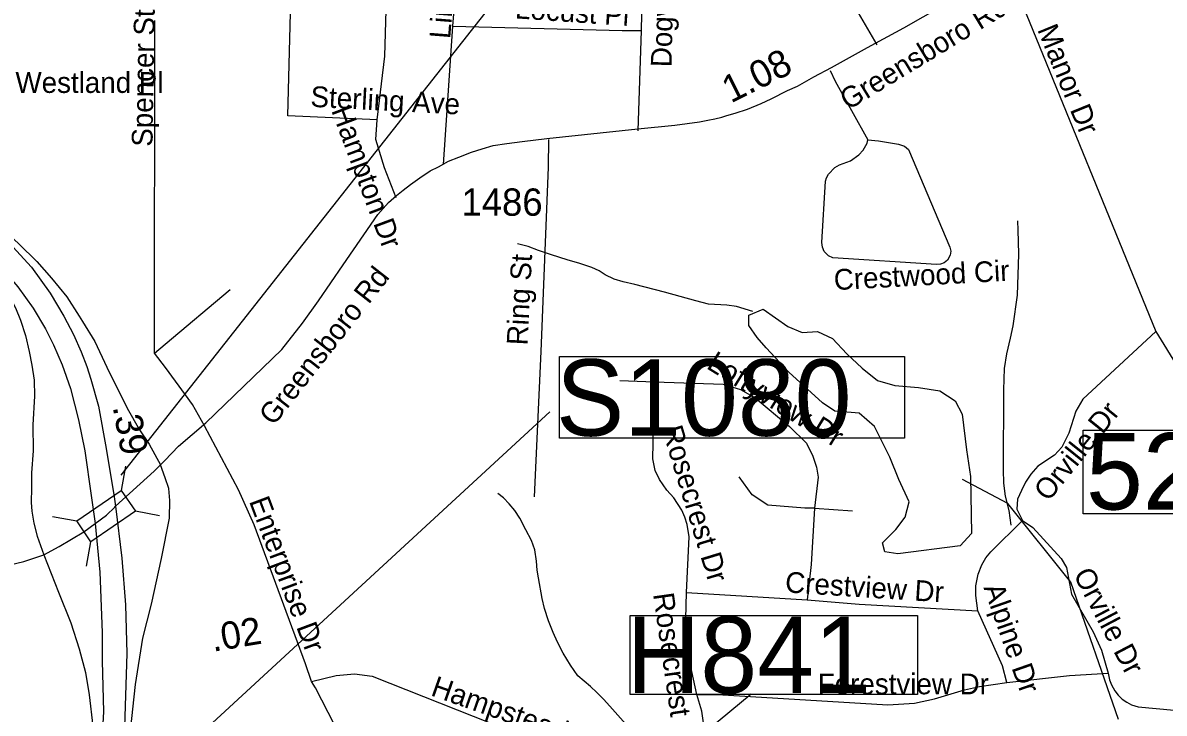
# Model space of a CAD drawing. Extents: x 1662474 to 1856135, y 779280 to 917889.
# Drawn here: x 1711418 to 1716644, y 813062 to 816221 of the extents above; entities that cross this region are included whole.
import ezdxf

# ---------------------------------------------------------------- set-up
doc = ezdxf.new("R2010")
doc.units = 0
for name, color, linetype in [('Exist Hydrographic Misc Water Feature', 7, 'Continuous'), ('Exist Hydrographic Pond Under 1500 Sq Ft', 7, 'Continuous'), ('Exist Road Non-System Structure Non-Sys NCDOT Number Label', 7, 'Continuous'), ('Exist Road Non-System Type 51', 7, 'Continuous'), ('Exist Road Non-System Type 51 Label', 7, 'Continuous'), ('Exist Road Primary Interstate Ramp 1 Lane Attributed', 7, 'Continuous'), ('Exist Road Primary US Divided Attributed', 7, 'Continuous'), ('Exist Road Primary US Mileage Hundredths English Label', 7, 'Continuous'), ('Exist Road Primary US Structure Ovrhead Sign CELL', 7, 'Continuous'), ('Exist Road Secondary Mileage Hundredths English Label', 7, 'Continuous'), ('Exist Road Secondary Structure Standard Bridge CELL', 7, 'Continuous'), ('Exist Road Secondary Structure Standard Bridge Number Label', 7, 'Continuous'), ('Exist Road Secondary Type 51 Attributed', 7, 'Continuous'), ('Exist Road Secondary Type 51 Label', 7, 'Continuous'), ('Exist Road Secondary Type 51 Number Label', 7, 'Continuous')]:
    doc.layers.add(name, color=color, linetype=linetype)

msp = doc.modelspace()

# ---------------------------------------------------------------- linework, layer by layer
at = {"layer": 'Exist Hydrographic Misc Water Feature'}
msp.add_line((1714761.2, 814899.8), (1714685.4, 814922.6), dxfattribs=at)
for points in [[(1715944.3, 813922.4), (1715934.9, 813988.4), (1715917.6, 814054.6), (1715910.2, 814114.7), (1715908.6, 814174.7), (1715910.2, 814540.8), (1715913.1, 814638.9), (1715923.7, 814706.7), (1715940.4, 814778.6), (1715952.9, 814834.5), (1715972.3, 814974.4), (1715978.1, 815162.4), (1715976.5, 815218.4), (1715975.1, 815272.4), (1715973.5, 815314.5)], [(1714685.4, 814922.6), (1714641.4, 814929), (1714557.3, 814933.8), (1714499.5, 814948.3), (1714355.9, 814987.7), (1714220.1, 815023), (1714166.2, 815035.5), (1714126.4, 815047.9), (1714084.5, 815068.3), (1714056.7, 815086.6), (1714022.9, 815100.9), (1713969.1, 815119.4), (1713911.1, 815136), (1713839.4, 815158.6), (1713779.5, 815179.2), (1713731.6, 815197.7), (1713683.7, 815210.1)], [(1716435.3, 813033.3), (1716216.3, 813661.3), (1715928.3, 814021.7), (1715720.3, 814131)], [(1714266.3, 812913.9), (1714105.8, 813093.4), (1714076.3, 813125.7), (1714046.5, 813156), (1714016.7, 813184.3), (1713988.8, 813208.6), (1713959.1, 813232.9), (1713925.6, 813281.2), (1713892.2, 813335.6), (1713866.6, 813385.8), (1713846.9, 813430), (1713825.5, 813484.2), (1713806, 813540.4), (1713796.5, 813586.5), (1713779.4, 813680.7), (1713773.6, 813716.8), (1713769.9, 813756.8), (1713762.5, 813808.9), (1713747, 813851.1), (1713721.4, 813901.3), (1713693.9, 813953.6), (1713670.3, 813989.9), (1713644.5, 814020.1), (1713618.7, 814046.4), (1713592.9, 814066.6)]]:
    msp.add_lwpolyline(points, dxfattribs=at)
at = {"layer": 'Exist Hydrographic Pond Under 1500 Sq Ft'}
msp.add_lwpolyline([(1715757, 814145.2), (1715761.7, 813883.7), (1715710.3, 813827.6), (1715425.2, 813790.3), (1715364.5, 813799.6), (1715355.1, 813841.6), (1715415.9, 813902.3), (1715457.9, 813958.4), (1715476.6, 814028.5), (1715429.9, 814131.2), (1715387.8, 814234), (1715317.7, 814374.1), (1715247.6, 814434.8), (1715135.5, 814444.2), (1715079.4, 814481.5), (1714925.2, 814621.6), (1714822.4, 814733.7), (1714780.3, 814780.4), (1714742.9, 814836.5), (1714742.9, 814883.2), (1714808.4, 814911.2), (1714920.5, 814831.8), (1714985.9, 814803.8), (1715056, 814808.5), (1715126.1, 814775.8), (1715191.6, 814705.7), (1715261.7, 814640.3), (1715331.7, 814584.3), (1715411.2, 814560.9), (1715518.7, 814551.6), (1715616.8, 814537.6), (1715686.9, 814490.9), (1715719.6, 814430.1), (1715738.3, 814266.7), (1715757, 814145.2)], dxfattribs=at)
at = {"layer": 'Exist Road Non-System Structure Non-Sys NCDOT Number Label'}
msp.add_line((1711805.1, 810722.8), (1714752.6, 813149.3), dxfattribs=at)
msp.add_lwpolyline([(1714198.2, 813508.5), (1715515.3, 813508.5), (1715515.3, 813147.3), (1714198.2, 813147.3)], close=True, dxfattribs=at)
at = {"layer": 'Exist Road Non-System Type 51'}
for p, q in [((1713386.9, 816205.4), (1713415.4, 816558.2)), ((1714251.1, 816186.8), (1714259.2, 816535.9)), ((1715928.5, 816468.9), (1716606.5, 814808.9)), ((1712020.5, 814709.7), (1712021.8, 816231.2)), ((1713344.9, 815572.6), (1713386.9, 816205.4)), ((1714235.9, 815727.2), (1714251.1, 816186.8)), ((1716606.5, 814808.9), (1716708.4, 814641.7)), ((1714151.9, 814583.7), (1714311, 814577.9)), ((1715042.8, 813999.4), (1715216.8, 813986.9)), ((1714457.6, 813614.1), (1715009.4, 813580))]:
    msp.add_line(p, q, dxfattribs=at)
for points in [[(1713039.9, 815777.1), (1712630.9, 815794.9), (1712662.1, 816972.6)], [(1713039.9, 815777.1), (1713075.4, 816068.7), (1713102.1, 816964.2)], [(1715186.6, 816353.7), (1715194.1, 816352.4), (1715231.6, 816285.8), (1715328.2, 816120.1)], [(1713386.9, 816205.4), (1714161.9, 816186.8), (1714251.1, 816186.8)], [(1715115.4, 816003.4), (1715136.9, 815954.5), (1715286.6, 815685.2)], [(1713127.2, 815419.6), (1713073.5, 815558.2), (1713034.1, 815687.6), (1713039.9, 815777.1)], [(1713761.4, 814051.9), (1713792.1, 814716.2), (1713825.4, 815560), (1713827, 815687.1)], [(1715286.6, 815685.2), (1715335.4, 815681), (1715428.2, 815666.1), (1715455.1, 815656.4), (1715473.4, 815641.7), (1715663.1, 815194.9), (1715666.6, 815176.4), (1715664, 815157.7), (1715651.9, 815135.6), (1715636.9, 815123.2), (1715619.9, 815116.8), (1715601, 815114.9), (1715127.2, 815146.1), (1715107.6, 815154.8), (1715087.6, 815174.5), (1715078.9, 815193.9), (1715076.6, 815215.2), (1715092.9, 815495.8), (1715097.6, 815512), (1715107, 815529.1), (1715136.4, 815559.5), (1715157.6, 815570.8), (1715207.2, 815588.9), (1715246.4, 815617.2), (1715265.9, 815637.7), (1715284.1, 815670.2), (1715286.6, 815685.2)], [(1712020.5, 814709.7), (1712070.4, 814749.9), (1712367.1, 815001)], [(1716606.5, 814808.9), (1716272.4, 814498.1), (1716240.1, 814443.2), (1716208.1, 814343.5), (1716175.8, 814278.9), (1716141.9, 814241.9), (1716066.1, 814192.1), (1716034.1, 814155.4), (1716009.6, 814118.1), (1715990.2, 814081), (1715972.6, 814040.6), (1715969.5, 813995.2), (1715996.2, 813944)], [(1712249.1, 814377.4), (1712195.5, 814474.8), (1712163.2, 814519.1), (1712071.6, 814644.2), (1712020.5, 814709.7)], [(1714457.6, 813614.1), (1714469.2, 813868.2), (1714459.9, 813925.4), (1714449.6, 813958.8), (1714436.1, 813990.8), (1714399.1, 814046.9), (1714367.1, 814082.6), (1714333, 814130.7), (1714314.1, 814171.6), (1714302.1, 814225.4), (1714311, 814577.9)], [(1714311, 814577.9), (1714624.6, 814566.9), (1714704.4, 814542.8), (1714770.9, 814505.2), (1714928, 814373.7), (1715006.2, 814297.4), (1715035.4, 814237.8), (1715051.9, 814187.6), (1715059.5, 814141.9), (1715042.8, 813999.4)], [(1712739.6, 813206.2), (1712712.9, 813287.4), (1712476.6, 813923.4), (1712405.5, 814083.2), (1712249.1, 814377.4)], [(1715042.8, 813999.4), (1714998.4, 814000.2), (1714828.6, 814013.9), (1714757.6, 814060.9), (1714697.4, 814143.5)], [(1715042.8, 813999.4), (1715028, 813741.7), (1715009.4, 813580)], [(1715790.5, 813529.6), (1715781, 813599.7), (1715781.2, 813645.1), (1715791.8, 813698.4), (1715809.1, 813740.7), (1715828, 813772.1), (1715850.9, 813799.9), (1715996.2, 813944)], [(1715996.2, 813944), (1716043.2, 813912), (1716172.9, 813769.8), (1716196.8, 813728), (1716219.4, 813606.5), (1716318.9, 813433.6), (1716356.9, 813350.4), (1716387.4, 813244.9)], [(1714504.6, 813147.2), (1714481.6, 813251.7), (1714459.5, 813378.4), (1714453.5, 813493.7), (1714457.6, 813614.1)], [(1715009.4, 813580), (1715247.1, 813560.6), (1715790.5, 813529.6)], [(1715924.4, 813201.2), (1715903.6, 813278.7), (1715790.5, 813529.6)], [(1712739.6, 813206.2), (1712853.2, 813234.1), (1712936.8, 813240.9), (1713018.1, 813230.7), (1713561.4, 813016.5)], [(1715924.4, 813201.2), (1716211.1, 813233.6), (1716387.4, 813244.9)], [(1716387.4, 813244.9), (1716393.9, 813213.9), (1716402.5, 813190.5), (1716418, 813163.2), (1716434, 813143.8), (1716452.1, 813125.9), (1716472.9, 813111.5), (1716495.1, 813100.2), (1716525.1, 813090), (1716690.5, 813075.6), (1716762.1, 813081.9), (1716845.9, 813133)], [(1712958.2, 812329.1), (1712959.6, 812670.6), (1712952.8, 812734.1), (1712942, 812785.8), (1712923.1, 812846.4), (1712902.9, 812895.5), (1712758, 813177.7), (1712739.6, 813206.2)], [(1714504.6, 813147.2), (1714598.9, 813146.9), (1715378.9, 813099.2), (1715500.8, 813107.9), (1715592.9, 813127.5), (1715729.6, 813169), (1715798.1, 813183.7), (1715924.4, 813201.2)], [(1714542.5, 812903.9), (1714539.6, 812984.8), (1714527.8, 813070.9), (1714504.6, 813147.2)]]:
    msp.add_lwpolyline(points, dxfattribs=at)
at = {"layer": 'Exist Road Primary Interstate Ramp 1 Lane Attributed'}
for points in [[(1711039.5, 815510.5), (1711250.2, 815346.4), (1711399.5, 815209.6), (1711482, 815128.2), (1711549.8, 815053), (1711619.8, 814967.4), (1711675.1, 814878.6), (1711691.8, 814853.6), (1711747.9, 814762.8), (1711803, 814645.8), (1711894.9, 814457.6), (1711952.3, 814359), (1711995.9, 814292.4), (1712048.2, 814198.3)], [(1710940.5, 815460.4), (1711193.9, 815186.3), (1711283, 815081.6), (1711356.1, 814970.5), (1711384.2, 814916.9), (1711407, 814860.7), (1711429.4, 814790.8), (1711446.6, 814717.2), (1711459.1, 814654.8), (1711469.1, 814585), (1711471.6, 814512.6), (1711464, 814381.5), (1711465.7, 814261.8), (1711457.2, 814160.8), (1711457.2, 814092.4), (1711455.5, 814025.7), (1711458.9, 813986.3), (1711468.2, 813931.3), (1711483.6, 813871.4), (1711514, 813786.3)], [(1711870.5, 812613.4), (1711933.3, 813192.9), (1711967.6, 813404.2), (1712007.6, 813561.2), (1712053.3, 813769.6), (1712089.2, 813953.8), (1712091.6, 814034.6), (1712086.8, 814089.3), (1712070.1, 814139.2), (1712048.2, 814198.3)], [(1711514, 813786.3), (1711580.8, 813615.3), (1711637.6, 813474.7), (1711675.5, 813355.8), (1711705.2, 813247.6), (1711721.5, 813144.9), (1711737.7, 813001.6), (1711751.2, 812755.6), (1711757.6, 812683.9)]]:
    msp.add_lwpolyline(points, dxfattribs=at)
at = {"layer": 'Exist Road Primary US Divided Attributed'}
for points in [[(1711039.5, 815510.5), (1711189.5, 815370.6), (1711337.8, 815233), (1711457.8, 815102.5)], [(1710940.5, 815460.4), (1711083.6, 815331.8), (1711218.6, 815202.6), (1711307.8, 815111.9), (1711395.4, 815012.8), (1711464.8, 814915.2), (1711521.3, 814819.9), (1711558.6, 814747.5), (1711598, 814656.5), (1711636.4, 814548.2), (1711673.1, 814403.9), (1711701.4, 814262.8), (1711730.8, 814057.3), (1711748.7, 813929)], [(1711457.8, 815102.5), (1711543.8, 814983.4), (1711606.2, 814878.3), (1711649.2, 814795), (1711684.4, 814715.4), (1711710.3, 814647.6), (1711729.6, 814590.7), (1711764.9, 814467.4), (1711800.2, 814273.4), (1711835.5, 814051.1), (1711842.5, 814008.4)], [(1711842.5, 814008.4), (1711870.5, 813771.3), (1711887.7, 813557.2), (1711893.4, 813334.5), (1711870.5, 812613.4)], [(1711748.7, 813929), (1711770.2, 813707.2), (1711781, 813431.5), (1711781, 813299), (1711787.3, 813069.4), (1711780.7, 812957.4), (1711770.8, 812795.9), (1711765.9, 812733.3), (1711757.6, 812683.9)]]:
    msp.add_lwpolyline(points, dxfattribs=at)
at = {"layer": 'Exist Road Primary US Structure Ovrhead Sign CELL'}
msp.add_line((1711950.1, 812708.4), (1713830.8, 814441.5), dxfattribs=at)
msp.add_lwpolyline([(1713875.3, 814693.6), (1715455.3, 814693.6), (1715455.3, 814319.5), (1713875.3, 814319.5)], close=True, dxfattribs=at)
at = {"layer": 'Exist Road Secondary Structure Standard Bridge CELL'}
for p, q in [((1711869.1, 814080.9), (1711889.9, 814192.2)), ((1711553.1, 813962), (1711664.4, 813941.2)), ((1711933.1, 813987.5), (1712044.4, 813966.8)), ((1711709, 813734.5), (1711729.8, 813845.7))]:
    msp.add_line(p, q, dxfattribs=at)
msp.add_lwpolyline([(1711664.4, 813941.2), (1711868.8, 814081.4), (1711934.3, 813985.8), (1711729.8, 813845.7)], close=True, dxfattribs=at)
at = {"layer": 'Exist Road Secondary Structure Standard Bridge Number Label'}
msp.add_line((1711868.1, 814150.7), (1714083.3, 816961.9), dxfattribs=at)
msp.add_lwpolyline([(1716273.6, 814356.2), (1716917.8, 814356.2), (1716917.8, 813973.9), (1716273.6, 813973.9)], close=True, dxfattribs=at)
at = {"layer": 'Exist Road Secondary Type 51 Attributed'}
for points in [[(1711842.5, 814008.4), (1712019.7, 814169.8), (1712067.7, 814217.8), (1712130.7, 814283.4), (1712256.2, 814390.4), (1712343.3, 814474.1), (1712517.5, 814641.6), (1712604.5, 814726.4), (1712698.1, 814846.1), (1712772.1, 814948.3), (1712885.2, 815113.6), (1712978.8, 815250.7), (1713044.1, 815344.2), (1713092, 815398.6), (1713129.6, 815430.5), (1713159.5, 815455.4), (1713193.3, 815481.9), (1713235.8, 815511.2), (1713282.8, 815543.5), (1713321, 815562.5), (1713366.5, 815587.5), (1713414.9, 815606.6), (1713472.1, 815628.6), (1713520.6, 815644.7), (1713571.9, 815659.4), (1713633.6, 815669.6), (1713704.3, 815678.4), (1713817.4, 815691.6), (1714234.7, 815735.4), (1714404, 815753), (1714515.9, 815768.7), (1714554, 815775.1), (1714587.1, 815781.9), (1714618.4, 815789.3), (1714641.8, 815796.3), (1714680.3, 815807.6), (1714736.5, 815825.5), (1714798.6, 815852.6), (1714844.6, 815873.8), (1714918.9, 815910.8), (1714964.5, 815932), (1715040.5, 815973.8), (1715121.4, 816016.5), (1715285.3, 816108.7), (1715452.3, 816197.9), (1715727.9, 816356.9)], [(1711748.7, 813929), (1711801.7, 813968.5), (1711838.4, 814004.7), (1711842.5, 814008.4)], [(1710704, 813538.9), (1710833.6, 813603.7), (1710926, 813642), (1711010.5, 813670.6), (1711132.8, 813693.3), (1711235.5, 813710), (1711314.6, 813729.4), (1711422.2, 813756.4), (1711514.1, 813786.4), (1711583.9, 813823.8), (1711696.9, 813892.2), (1711748.7, 813929)]]:
    msp.add_lwpolyline(points, dxfattribs=at)

# ---------------------------------------------------------------- texts
at = {"layer": 'Exist Road Non-System Structure Non-Sys NCDOT Number Label'}
msp.add_text('H841', height=350, dxfattribs=at).set_placement((1714182.2, 813153.4))
at = {"layer": 'Exist Road Non-System Type 51 Label'}
for s, rotation, p in [('Lindale Dr', 85.471, (1713374.6, 816145.8)), ('Dogwood Cir', 88.4934, (1714388.1, 816017.3)), ('Locust Pl', 356.1239, (1713669.9, 816241.9)), ('Spencer St', 89.0166, (1712011.4, 815653.6)), ('Manor Dr', 292.1714, (1716062.1, 816190.8)), ('Sterling Ave', 356.9951, (1712733.4, 815837.2)), ('Hampton Dr', 290.4222, (1712829.3, 815820.6)), ('Ring St', 87.0081, (1713728.2, 814743.6)), ('Crestwood Cir', 3.0681, (1715133.8, 814997.6)), ('Loftyview Dr', 328.2686, (1714543.7, 814642.3)), ('Orville Dr', 51.1818, (1716114, 814026)), ('Rosecrest Dr', 286.8927, (1714343.5, 814361.7)), ('Enterprise Dr', 290.607, (1712452.6, 814031.9)), ('Crestview Dr', 356.3424, (1714906.5, 813614.7)), ('Orville Dr', 297.6651, (1716226.2, 813696.5)), ('Alpine Dr', 289.2819, (1715816.2, 813636.5)), ('Rosecrest Dr', 278.1255, (1714303.7, 813606.6)), ('Hampstead Dr', 340.6223, (1713281.3, 813144))]:
    msp.add_text(s, height=95, rotation=rotation, dxfattribs=at).set_placement(p)
for s, p in [('Westland Pl', (1711384.2, 815900.4)), ('Forestview Dr', (1715057.9, 813147.9))]:
    msp.add_text(s, height=95, dxfattribs=at).set_placement(p)
at = {"layer": 'Exist Road Primary US Mileage Hundredths English Label'}
msp.add_text('.39', height=125, rotation=280.3109, dxfattribs=at).set_placement((1711829.1, 814463.8))
at = {"layer": 'Exist Road Primary US Structure Ovrhead Sign CELL'}
msp.add_text('S1080', height=350, dxfattribs=at).set_placement((1713859.3, 814331.1))
at = {"layer": 'Exist Road Secondary Mileage Hundredths English Label'}
for s, rotation, p in [('1.08', 26.5005, (1714659.7, 815851.4)), ('.02', 9.4734, (1712288.9, 813342.4))]:
    msp.add_text(s, height=125, rotation=rotation, dxfattribs=at).set_placement(p)
at = {"layer": 'Exist Road Secondary Structure Standard Bridge Number Label'}
msp.add_text('52', height=350, dxfattribs=at).set_placement((1716286.2, 813993.7))
at = {"layer": 'Exist Road Secondary Type 51 Label'}
for rotation, p in [(31.3261, (1715196.8, 815819.4)), (51.9968, (1712566.6, 814373.1))]:
    msp.add_text('Greensboro Rd', height=95, rotation=rotation, dxfattribs=at).set_placement(p)
at = {"layer": 'Exist Road Secondary Type 51 Number Label'}
msp.add_text('1486', height=125, dxfattribs=at).set_placement((1713426.1, 815338.2))

doc.saveas('drawing.dxf')
